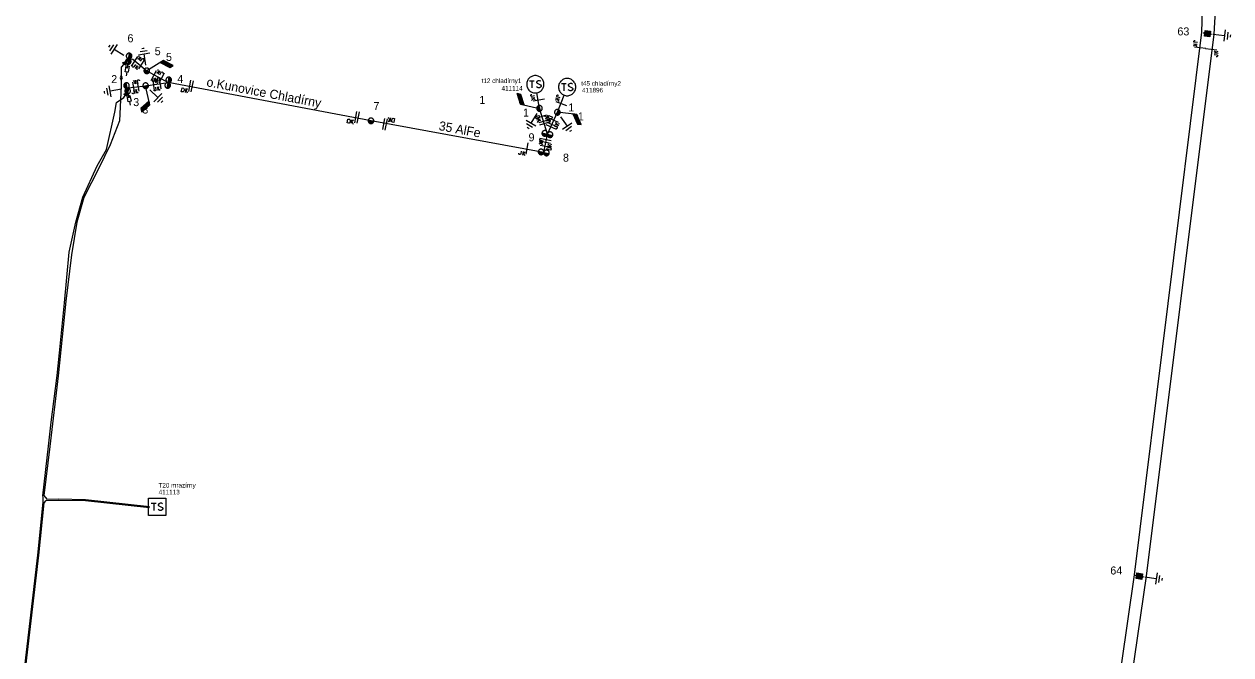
# Model space of a CAD drawing. Extents: x -540879 to -537255, y -1184046 to -1180016.
# Drawn here: x -540271.5 to -540007.7, y -1183547.5 to -1183409.6 of the extents above; entities that cross this region are included whole.
import ezdxf

# ---------------------------------------------------------------- set-up
doc = ezdxf.new("R2010")
doc.units = 0
for name, color, linetype in [('Default', 7, 'Continuous'), ('Vrstva 1', 7, 'Continuous'), ('Vrstva 11', 7, 'Continuous'), ('Vrstva 12', 7, 'Continuous'), ('Vrstva 13', 7, 'Continuous'), ('Vrstva 14', 7, 'Continuous'), ('Vrstva 15', 7, 'Continuous'), ('Vrstva 16', 7, 'Continuous'), ('Vrstva 18', 7, 'Continuous'), ('Vrstva 19', 7, 'Continuous'), ('Vrstva 2', 7, 'Continuous'), ('Vrstva 25', 7, 'Continuous'), ('Vrstva 26', 7, 'Continuous'), ('Vrstva 27', 7, 'Continuous'), ('Vrstva 4', 7, 'Continuous'), ('Vrstva 5', 7, 'Continuous'), ('Vrstva 52', 7, 'Continuous'), ('Vrstva 53', 7, 'Continuous'), ('Vrstva 54', 7, 'Continuous'), ('Vrstva 6', 7, 'Continuous')]:
    doc.layers.add(name, color=color, linetype=linetype)

# ---------------------------------------------------------------- blocks, each defined once
blk = doc.blocks.new('VN850')
at = {"layer": 'Vrstva 15'}
for points in [[(-0.56, 1.43), (-0.56, -1.07)], [(-0.01, 1.43), (-0.01, -1.07)], [(-2.09, -0.54), (-1.78, -0.54)], [(-2.09, -1.41), (-2.09, -0.54)], [(-1.78, -1.41), (-2.09, -1.41)], [(-1.78, -0.54), (-1.66, -0.6)], [(-1.67, -1.35), (-1.78, -1.41)], [(-1.59, -1.2), (-1.67, -1.35)], [(-1.66, -0.6), (-1.59, -0.75)], [(-1.59, -0.75), (-1.55, -0.96)], [(-1.55, -0.96), (-1.59, -1.2)], [(-1.26, -0.54), (-1.26, -1.41)], [(-0.85, -0.54), (-1.26, -1.09)], [(-1.13, -0.92), (-0.77, -1.41)]]:
    blk.add_lwpolyline(points, dxfattribs=at)
blk = doc.blocks.new('VN840')
at = {"layer": 'Vrstva 15'}
for points in [[(-0.01, 1.41), (-0.01, -1.09)], [(-1.51, -1.24), (-1.51, -1.15)], [(-1.48, -1.35), (-1.51, -1.24)], [(-1.33, -1.42), (-1.48, -1.35)], [(-1.27, -1.42), (-1.33, -1.42)], [(-1.13, -1.35), (-1.27, -1.42)], [(-1.09, -1.24), (-1.13, -1.35)], [(-1.09, -0.59), (-1.09, -1.24)], [(-0.68, -0.59), (-0.68, -1.42)], [(-0.68, -1.11), (-0.27, -0.59)], [(-0.54, -0.94), (-0.2, -1.42)]]:
    blk.add_lwpolyline(points, dxfattribs=at)
blk = doc.blocks.new('VN440')
at = {"layer": 'Vrstva 2'}
for points in [[(1.22, 0), (1.21, 0.13), (1.19, 0.25), (1.16, 0.38), (1.11, 0.5), (1.05, 0.61), (0.98, 0.72), (0.9, 0.82), (0.81, 0.91), (0.71, 0.99), (0.6, 1.06), (0.49, 1.12), (0.37, 1.16), (0.25, 1.2), (0.12, 1.22), (-0.01, 1.22), (-0.14, 1.22), (-0.26, 1.2), (-0.39, 1.16), (-0.51, 1.12), (-0.62, 1.06), (-0.73, 0.99), (-0.83, 0.91), (-0.92, 0.82), (-1, 0.72), (-1.07, 0.61), (-1.13, 0.5), (-1.18, 0.38), (-1.21, 0.25), (-1.23, 0.13), (-1.24, 0), (-1.23, -0.13), (-1.21, -0.26), (-1.18, -0.38), (-1.13, -0.5), (-1.07, -0.62), (-1, -0.73), (-0.92, -0.83), (-0.83, -0.92), (-0.73, -1), (-0.62, -1.07), (-0.51, -1.13), (-0.39, -1.17), (-0.26, -1.2), (-0.14, -1.23), (-0.01, -1.23), (0.12, -1.23), (0.25, -1.2), (0.37, -1.17), (0.49, -1.13), (0.6, -1.07), (0.71, -1), (0.81, -0.92), (0.9, -0.83), (0.98, -0.73), (1.05, -0.62), (1.11, -0.5), (1.16, -0.38), (1.19, -0.26), (1.21, -0.13), (1.22, 0)], [(-1.24, 0), (1.22, 0)], [(-1.18, -0.34), (1.1, -0.34)], [(-1.01, -0.63), (0.97, -0.63)], [(-0.74, -0.92), (0.68, -0.92)]]:
    blk.add_lwpolyline(points, dxfattribs=at)
blk = doc.blocks.new('VN870')
at = {"layer": 'Vrstva 4'}
for points in [[(0, -0.25), (0.5, 0), (0, 0.25), (-0.5, 0), (0, -0.25)], [(0.37, 0), (0, 0.19), (-0.36, 0), (0, -0.19), (0.37, 0)], [(0.24, 0), (0, 0.12), (-0.25, 0), (0, -0.12), (0.24, 0)], [(0.12, 0), (0, 0.06), (-0.13, 0), (0, -0.06), (0.12, 0)]]:
    blk.add_lwpolyline(points, dxfattribs=at)
blk = doc.blocks.new('VN890')
at = {"layer": 'Vrstva 4'}
for points in [[(-0.41, 0.41), (0.41, 0)], [(-0.41, -0.41), (-0.41, 0.41)], [(0.41, 0), (-0.41, -0.41)], [(-0.34, 0.31), (0.27, 0), (-0.34, -0.3), (-0.34, 0.31)], [(-0.26, 0.2), (0.1, 0), (-0.26, -0.18), (-0.26, 0.2)], [(-0.19, 0.09), (-0.04, 0), (-0.19, -0.08), (-0.19, 0.09)], [(-0.16, -0.01), (-0.16, 0.03), (-0.13, 0.01), (-0.16, -0.01)]]:
    blk.add_lwpolyline(points, dxfattribs=at)
blk = doc.blocks.new('VN820')
at = {"layer": 'Vrstva 13'}
for points in [[(0, 0), (0, -2.1)], [(-0.32, -1.63), (0.34, -1.63)], [(-0.32, -2.95), (-0.32, -1.63)], [(0, -2.1), (-0.12, -1.86)], [(0, -2.1), (0.12, -1.86)], [(0.34, -1.63), (0.34, -2.95)], [(0.34, -2.95), (-0.32, -2.95)], [(0, -2.95), (0, -3.75)]]:
    blk.add_lwpolyline(points, dxfattribs=at)
blk = doc.blocks.new('VN810')
at = {"layer": 'Vrstva 14'}
for points in [[(0, -1.25), (0, -3.75)], [(1.25, -3.75), (-1.25, -3.75)], [(0.77, -4.37), (-0.8, -4.37)], [(0, -5), (-0.25, -5)], [(0.27, -5), (0, -5)]]:
    blk.add_lwpolyline(points, dxfattribs=at)
blk = doc.blocks.new('VN640')
at = {"layer": 'Vrstva 6'}
for points in [[(-1.89, 1.89), (1.89, 1.89)], [(-1.89, -1.89), (-1.89, 1.89)], [(-1.26, 0.79), (-0.22, 0.79)], [(-0.73, 0.79), (-0.73, -0.79)], [(1.2, 0.66), (0.94, 0.79), (0.66, 0.79), (0.41, 0.66), (0.28, 0.47), (0.28, 0.41), (0.41, 0.22), (1.13, -0.16), (1.26, -0.32), (1.26, -0.47), (1.13, -0.66), (0.91, -0.79), (0.63, -0.79), (0.5, -0.73), (0.28, -0.6)], [(1.89, 1.89), (1.89, -1.89)], [(1.89, -1.89), (-1.89, -1.89)]]:
    blk.add_lwpolyline(points, dxfattribs=at)
blk = doc.blocks.new('VN610')
at = {"layer": 'Vrstva 6'}
for points in [[(1.88, 0), (1.87, 0.2), (1.84, 0.39), (1.79, 0.58), (1.72, 0.77), (1.63, 0.94), (1.52, 1.11), (1.4, 1.26), (1.26, 1.4), (1.1, 1.53), (0.94, 1.63), (0.76, 1.72), (0.58, 1.8), (0.39, 1.85), (0.19, 1.88), (-0.01, 1.89), (-0.21, 1.88), (-0.4, 1.85), (-0.59, 1.8), (-0.78, 1.72), (-0.95, 1.63), (-1.12, 1.53), (-1.27, 1.4), (-1.41, 1.26), (-1.54, 1.11), (-1.64, 0.94), (-1.73, 0.77), (-1.8, 0.58), (-1.86, 0.39), (-1.89, 0.2), (-1.9, 0), (-1.89, -0.2), (-1.86, -0.39), (-1.8, -0.58), (-1.73, -0.77), (-1.64, -0.95), (-1.54, -1.11), (-1.41, -1.27), (-1.27, -1.41), (-1.12, -1.53), (-0.95, -1.64), (-0.78, -1.73), (-0.59, -1.8), (-0.4, -1.85), (-0.21, -1.88), (-0.01, -1.89), (0.19, -1.88), (0.39, -1.85), (0.58, -1.8), (0.76, -1.73), (0.94, -1.64), (1.1, -1.53), (1.26, -1.41), (1.4, -1.27), (1.52, -1.11), (1.63, -0.95), (1.72, -0.77), (1.79, -0.58), (1.84, -0.39), (1.87, -0.2), (1.88, 0)], [(-1.27, 0.78), (-0.26, 0.78)], [(-0.76, 0.78), (-0.76, -0.79)], [(1.19, 0.66), (0.94, 0.78), (0.62, 0.78), (0.37, 0.66), (0.24, 0.47), (0.24, 0.4), (0.37, 0.22), (1.12, -0.16), (1.25, -0.32), (1.25, -0.48), (1.12, -0.67), (0.87, -0.79), (0.62, -0.79), (0.49, -0.73), (0.24, -0.6)]]:
    blk.add_lwpolyline(points, dxfattribs=at)
blk = doc.blocks.new('VN450')
at = {"layer": 'Vrstva 2'}
for points in [[(0, 0), (-0.01, 0.13), (-0.03, 0.25), (-0.06, 0.38), (-0.11, 0.5), (-0.16, 0.61), (-0.23, 0.72), (-0.31, 0.82), (-0.4, 0.91), (-0.5, 0.99), (-0.61, 1.06), (-0.72, 1.11), (-0.84, 1.16), (-0.97, 1.19), (-1.09, 1.21), (-1.22, 1.22), (-1.35, 1.21), (-1.47, 1.19), (-1.59, 1.16), (-1.71, 1.11), (-1.83, 1.06), (-1.93, 0.99), (-2.03, 0.91), (-2.12, 0.82), (-2.2, 0.72), (-2.27, 0.61), (-2.33, 0.5), (-2.38, 0.38), (-2.41, 0.25), (-2.43, 0.13), (-2.44, 0), (-2.43, -0.13), (-2.41, -0.25), (-2.38, -0.38), (-2.33, -0.5), (-2.27, -0.61), (-2.2, -0.72), (-2.12, -0.82), (-2.03, -0.91), (-1.93, -0.99), (-1.83, -1.06), (-1.71, -1.11), (-1.59, -1.16), (-1.47, -1.19), (-1.35, -1.21), (-1.22, -1.22), (-1.09, -1.21), (-0.97, -1.19), (-0.84, -1.16), (-0.72, -1.11), (-0.61, -1.06), (-0.5, -0.99), (-0.4, -0.91), (-0.31, -0.82), (-0.23, -0.72), (-0.16, -0.61), (-0.11, -0.5), (-0.06, -0.38), (-0.03, -0.25), (-0.01, -0.13), (0, 0)], [(-2.44, 0), (2.44, 0)], [(2.44, 0), (2.43, 0.13), (2.41, 0.25), (2.38, 0.38), (2.33, 0.5), (2.27, 0.61), (2.2, 0.72), (2.12, 0.82), (2.03, 0.91), (1.94, 0.99), (1.83, 1.06), (1.71, 1.11), (1.6, 1.16), (1.47, 1.19), (1.35, 1.21), (1.22, 1.22), (1.09, 1.21), (0.97, 1.19), (0.84, 1.16), (0.72, 1.11), (0.61, 1.06), (0.5, 0.99), (0.4, 0.91), (0.31, 0.82), (0.23, 0.72), (0.16, 0.61), (0.11, 0.5), (0.06, 0.38), (0.03, 0.25), (0.01, 0.13), (0, 0), (0.01, -0.13), (0.03, -0.25), (0.06, -0.38), (0.11, -0.5), (0.16, -0.61), (0.23, -0.72), (0.31, -0.82), (0.4, -0.91), (0.5, -0.99), (0.61, -1.06), (0.72, -1.11), (0.84, -1.16), (0.97, -1.19), (1.09, -1.21), (1.22, -1.22), (1.35, -1.21), (1.47, -1.19), (1.6, -1.16), (1.71, -1.11), (1.83, -1.06), (1.94, -0.99), (2.03, -0.91), (2.12, -0.82), (2.2, -0.72), (2.27, -0.61), (2.33, -0.5), (2.38, -0.38), (2.41, -0.25), (2.43, -0.13), (2.44, 0)], [(-2.4, -0.31), (-0.04, -0.31)], [(-2.26, -0.61), (-0.17, -0.61)], [(-2.01, -0.92), (-0.42, -0.92)], [(0.04, -0.31), (2.4, -0.31)], [(0.17, -0.61), (2.27, -0.61)], [(0.42, -0.92), (2.02, -0.92)]]:
    blk.add_lwpolyline(points, dxfattribs=at)
blk = doc.blocks.new('VN001')
at = {"layer": 'Default'}
for p, q in [((1.73, 3.03), (4.14, 3.03)), ((1.76, 3.08), (4.17, 3.08)), ((1.79, 3.13), (4.2, 3.13)), ((1.82, 3.18), (4.23, 3.18)), ((1.85, 3.23), (4.26, 3.23)), ((1.87, 3.28), (4.29, 3.28)), ((1.9, 3.33), (4.32, 3.33)), ((1.93, 3.38), (4.35, 3.38)), ((1.96, 3.43), (4.37, 3.43)), ((1.99, 3.48), (4.4, 3.48)), ((2.02, 3.53), (4.43, 3.53)), ((2.05, 3.58), (4.46, 3.58)), ((2.07, 3.63), (4.49, 3.63)), ((2.1, 3.68), (4.52, 3.68)), ((2.13, 3.73), (2.54, 3.73))]:
    blk.add_line(p, q, dxfattribs=at)
blk.add_lwpolyline([(2.13, 3.73), (0, 0)], dxfattribs=at)
blk.add_lwpolyline([(4.55, 3.73), (2.13, 3.73), (1.7, 2.98), (4.12, 2.99)], close=True, dxfattribs=at)
blk = doc.blocks.new('VN470')
at = {"layer": 'Vrstva 2'}
for points in [[(-1.23, 1.22), (1.23, 1.22)], [(-1.23, -1.23), (-1.23, 1.22)], [(-0.92, 0.9), (0.92, 0.9)], [(-0.92, -0.95), (-0.92, 0.9)], [(-0.61, 0.61), (0.61, 0.61)], [(-0.61, -0.62), (-0.61, 0.61)], [(-0.31, -0.27), (-0.31, 0.34)], [(-0.31, 0.34), (0.31, 0.34)], [(0, 1.22), (0, 1.97)], [(0.31, 0.34), (0.31, -0.27)], [(0.61, 0.61), (0.61, -0.62)], [(0.92, 0.9), (0.92, -0.95)], [(1.23, 1.22), (1.23, -1.23)], [(1.23, -1.23), (-1.23, -1.23)], [(0.92, -0.95), (-0.92, -0.95)], [(0.61, -0.62), (-0.61, -0.62)], [(0.31, -0.27), (-0.31, -0.27)], [(0, -1.23), (0, -1.98)]]:
    blk.add_lwpolyline(points, dxfattribs=at)

msp = doc.modelspace()

# ---------------------------------------------------------------- linework, layer by layer
at = {"layer": 'Vrstva 1'}
for points in [[(-540012.36, -1183354.43), (-540014.17, -1183411.34), (-540028.85, -1183530.04), (-540045.72, -1183647.03)], [(-540008.15, -1183354.48), (-540011.44, -1183411.77), (-540026.2, -1183530.3), (-540043.23, -1183647.3)]]:
    msp.add_lwpolyline(points, dxfattribs=at)
at = {"layer": 'Vrstva 4'}
for points in [[(-540158.86, -1183428), (-540159.45, -1183424.58)], [(-540154.96, -1183428.84), (-540153.49, -1183425.08)], [(-540157.13, -1183433.61), (-540158.86, -1183428)], [(-540157.13, -1183433.61), (-540154.96, -1183428.84)], [(-540157.93, -1183437.63), (-540157.13, -1183433.61)]]:
    msp.add_lwpolyline(points, dxfattribs=at)
at = {"layer": 'Vrstva 5'}
for points in [[(-540248.69, -1183417.14), (-540250.29, -1183418.96), (-540250.31, -1183421.31)], [(-540250.31, -1183421.31), (-540250.32, -1183423.04), (-540250.63, -1183429.18), (-540250.71, -1183430.71), (-540252.75, -1183436), (-540255.17, -1183441.06), (-540258.47, -1183447.51), (-540259.99, -1183452.91), (-540261.21, -1183460), (-540262.41, -1183470.18), (-540264.1, -1183486.46), (-540265.94, -1183501.93), (-540267.2, -1183512.64), (-540266.56, -1183513.47), (-540264.04, -1183513.41), (-540258.11, -1183513.52), (-540244.1, -1183515.07)], [(-540271.54, -1183551.28), (-540268.57, -1183525.7), (-540267.39, -1183514.12), (-540267.38, -1183513.03), (-540267.46, -1183512.71), (-540266.19, -1183501.9), (-540265.64, -1183496.65), (-540264.34, -1183486.43), (-540263.84, -1183481.48), (-540262.68, -1183470.56), (-540261.66, -1183459.47), (-540260.23, -1183452.85), (-540258.7, -1183447.41), (-540255.58, -1183440.58), (-540253.5, -1183437.02), (-540251.7, -1183428.85), (-540251.34, -1183426.69), (-540249.73, -1183425.64), (-540248.73, -1183424.07), (-540248.74, -1183423.66), (-540249.03, -1183423.61)], [(-540271.29, -1183551.3), (-540268.32, -1183525.73), (-540267.15, -1183514.23), (-540266.69, -1183513.72), (-540264.04, -1183513.66), (-540258.12, -1183513.77), (-540244.13, -1183515.31)]]:
    msp.add_lwpolyline(points, dxfattribs=at)
at = {"layer": 'Vrstva 52'}
for points in [[(-540248.69, -1183417.14), (-540247.79, -1183417.27), (-540244.72, -1183419.78)], [(-540244.72, -1183419.77), (-540240.04, -1183422.37)], [(-540249.03, -1183423.61), (-540248.15, -1183423.44), (-540244.97, -1183423.04)], [(-540244.97, -1183423.04), (-540240.04, -1183422.37)], [(-540195.7, -1183430.72), (-540240.04, -1183422.37)], [(-540157.93, -1183437.63), (-540195.7, -1183430.72)]]:
    msp.add_lwpolyline(points, dxfattribs=at)

# ---------------------------------------------------------------- block references
at = {"layer": 'Vrstva 11'}
for p, rotation in [((-540244.72, -1183419.77), -28.299599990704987), ((-540244.97, -1183423.04), -137.72051106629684), ((-540158.86, -1183428), 107.19590279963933), ((-540154.97, -1183428.84), -66.57340553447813)]:
    msp.add_blockref('VN001', p, dxfattribs=dict(at, rotation=rotation))
at = {"layer": 'Vrstva 13'}
for name, p, xscale, yscale, rotation in [('VN470', (-540012.82, -1183411.65), 0.49999999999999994, 0.49999999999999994, 82.98433892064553), ('VN450', (-540248.68, -1183417.14), 0.5, 0.5, 81.8771138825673), ('VN440', (-540244.72, -1183419.78), 0.5, 0.5, -28.316347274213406), ('VN450', (-540240.04, -1183422.37), 0.5000000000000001, 0.5, 79.52871113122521), ('VN450', (-540249.03, -1183423.61), 0.5, 0.5, -78.54001944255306), ('VN440', (-540244.97, -1183423.04), 0.49999999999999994, 0.5000000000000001, 10.003794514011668), ('VN440', (-540158.86, -1183428), 0.5, 0.5, -72.44218613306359), ('VN440', (-540154.96, -1183428.84), 0.49999999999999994, 0.5, 65.62446113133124), ('VN440', (-540195.7, -1183430.72), 0.49999999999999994, 0.49999999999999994, -11.620397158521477), ('VN450', (-540157.13, -1183433.61), 0.5, 0.5, -14.150816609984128), ('VN450', (-540157.93, -1183437.63), 0.5, 0.5, -10.367486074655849), ('VN470', (-540027.73, -1183530.3), 0.5, 0.5, 81.76570554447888)]:
    msp.add_blockref(name, p, dxfattribs=dict(at, xscale=xscale, yscale=yscale, rotation=rotation))
at = {"layer": 'Vrstva 15'}
for p, rotation in [((-540012.82, -1183411.65), 83.96296944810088), ((-540248.69, -1183417.15), -123.28151660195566), ((-540244.72, -1183419.77), -170.71573883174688), ((-540249.03, -1183423.61), -79.8778555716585), ((-540244.97, -1183423.04), 45.79327784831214), ((-540158.86, -1183428), -29.87806100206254), ((-540154.96, -1183428.84), 34.77296112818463), ((-540027.73, -1183530.3), 81.76570561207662)]:
    msp.add_blockref('VN810', p, dxfattribs=dict(at, rotation=rotation))
at = {"layer": 'Vrstva 16'}
for p, rotation in [((-540248.69, -1183417.14), -8.012644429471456), ((-540249.03, -1183423.61), 10.543247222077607)]:
    msp.add_blockref('VN820', p, dxfattribs=dict(at, rotation=rotation))
at = {"layer": 'Vrstva 18'}
for name, p, rotation in [('VN840', (-540014.59, -1183414.77), -97.0508000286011), ('VN840', (-540247.3, -1183417.59), 146.9457833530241), ('VN840', (-540245.95, -1183418.47), -33.05421664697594), ('VN840', (-540011.85, -1183415.08), 82.90211393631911), ('VN840', (-540246.64, -1183423.18), 9.828766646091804), ('VN840', (-540247.6, -1183423.35), -170.17123335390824), ('VN840', (-540243.1, -1183420.67), 151.01294718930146), ('VN840', (-540241.58, -1183421.52), -28.98705281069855), ('VN840', (-540241.81, -1183422.61), 7.7573916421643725), ('VN840', (-540243.21, -1183422.8), -172.242608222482), ('VN850', (-540234.86, -1183423.35), -10.67036096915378), ('VN840', (-540159.17, -1183426.23), -80.23665277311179), ('VN840', (-540154.22, -1183426.94), -111.41374716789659), ('VN850', (-540198.58, -1183430.18), -10.670361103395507), ('VN850', (-540192.87, -1183431.24), 169.631886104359), ('VN850', (-540157.81, -1183431.39), -72.79968324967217), ('VN840', (-540158.34, -1183429.71), 107.20031668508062), ('VN850', (-540156.42, -1183432.06), -114.37335558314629), ('VN840', (-540155.74, -1183430.55), 65.62664441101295), ('VN850', (-540157.37, -1183434.82), 78.65170828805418), ('VN840', (-540157.67, -1183436.32), -101.34829171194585), ('VN840', (-540161.66, -1183436.95), -10.368113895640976)]:
    msp.add_blockref(name, p, dxfattribs=dict(at, rotation=rotation))
at = {"layer": 'Vrstva 19'}
for name, p, rotation in [('VN890', (-540249.44, -1183418), 48.45101103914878), ('VN870', (-540250.31, -1183421.31), 89.55106940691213), ('VN890', (-540249.18, -1183424.77), 57.50519991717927)]:
    msp.add_blockref(name, p, dxfattribs=dict(at, rotation=rotation))
at = {"layer": 'Vrstva 25'}
for name, p in [('VN610', (-540159.77, -1183422.72)), ('VN610', (-540152.81, -1183423.34)), ('VN640', (-540242.48, -1183515.15))]:
    msp.add_blockref(name, p, dxfattribs=at)

# ---------------------------------------------------------------- texts
at = {"layer": 'Vrstva 12'}
for s, p in [('5', (-540240.52, -1183417.62)), ('1', (-540172.01, -1183427.02)), ('3', (-540245.69, -1183429.13)), ('1', (-540150.48, -1183430.63))]:
    msp.add_text(s, height=1.75, dxfattribs=at).set_placement(p)
at = {"layer": 'Vrstva 14'}
for s, p in [('63', (-540019.4, -1183412.04)), ('6', (-540248.94, -1183413.54)), ('5', (-540242.99, -1183416.38)), ('2', (-540252.5, -1183422.47)), ('4', (-540238.05, -1183422.42)), ('3', (-540247.68, -1183427.5)), ('7', (-540195.17, -1183428.36)), ('1', (-540152.56, -1183428.67)), ('1', (-540162.46, -1183429.79)), ('9', (-540161.26, -1183435.19)), ('8', (-540153.73, -1183439.65)), ('64', (-540034.07, -1183529.93))]:
    msp.add_text(s, height=1.75, dxfattribs=at).set_placement(p)
at = {"layer": 'Vrstva 26'}
for s, p in [('411114', (-540167.16, -1183424.1)), ('411896', (-540149.57, -1183424.51)), ('411113', (-540242.13, -1183512.42))]:
    msp.add_text(s, height=1, dxfattribs=at).set_placement(p)
at = {"layer": 'Vrstva 27'}
for s, p in [('t12 chladírny1', (-540171.51, -1183422.45)), ('t45 chladírny2', (-540149.74, -1183423.04)), ('T20 mrazírny', (-540242.16, -1183510.93))]:
    msp.add_text(s, height=1, dxfattribs=at).set_placement(p)
at = {"layer": 'Vrstva 53'}
msp.add_text('35 AlFe', height=2, rotation=349.632, dxfattribs=at).set_placement((-540181, -1183432.73))
at = {"layer": 'Vrstva 54'}
msp.add_text('o.Kunovice Chladírny', height=2, rotation=349.33, dxfattribs=at).set_placement((-540231.78, -1183423.14))

doc.saveas('drawing.dxf')
